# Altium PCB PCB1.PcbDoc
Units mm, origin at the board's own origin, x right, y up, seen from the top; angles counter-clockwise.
Board outline 140.5 x 67.5 mm, 2 copper layers (Top Layer, Bottom Layer); 70 components, 64 nets, 271 pads, 0 vias.
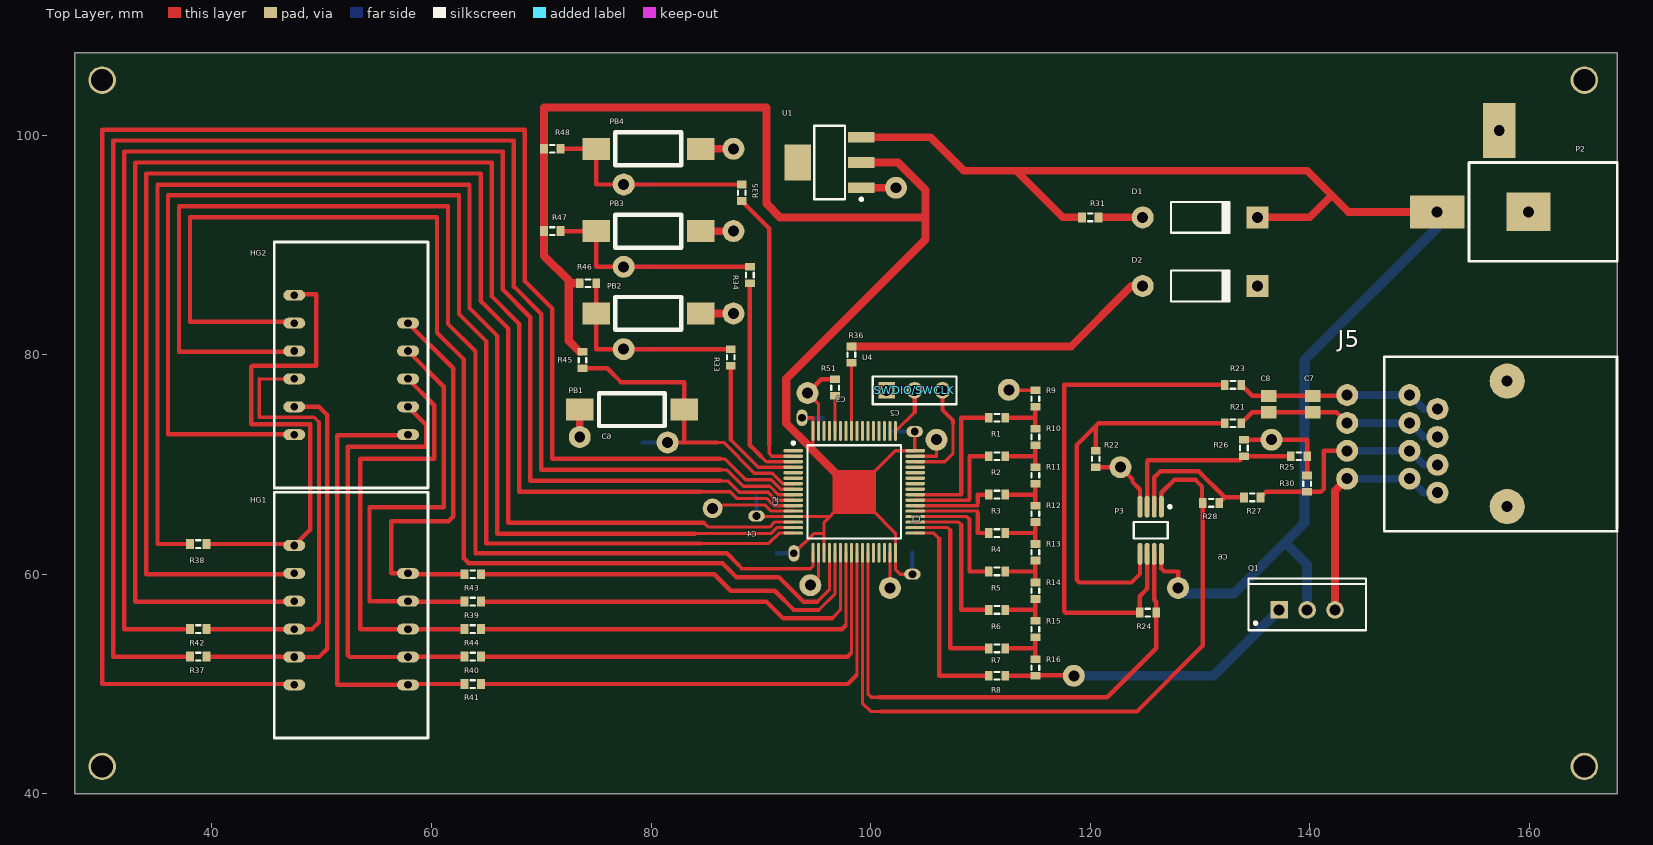
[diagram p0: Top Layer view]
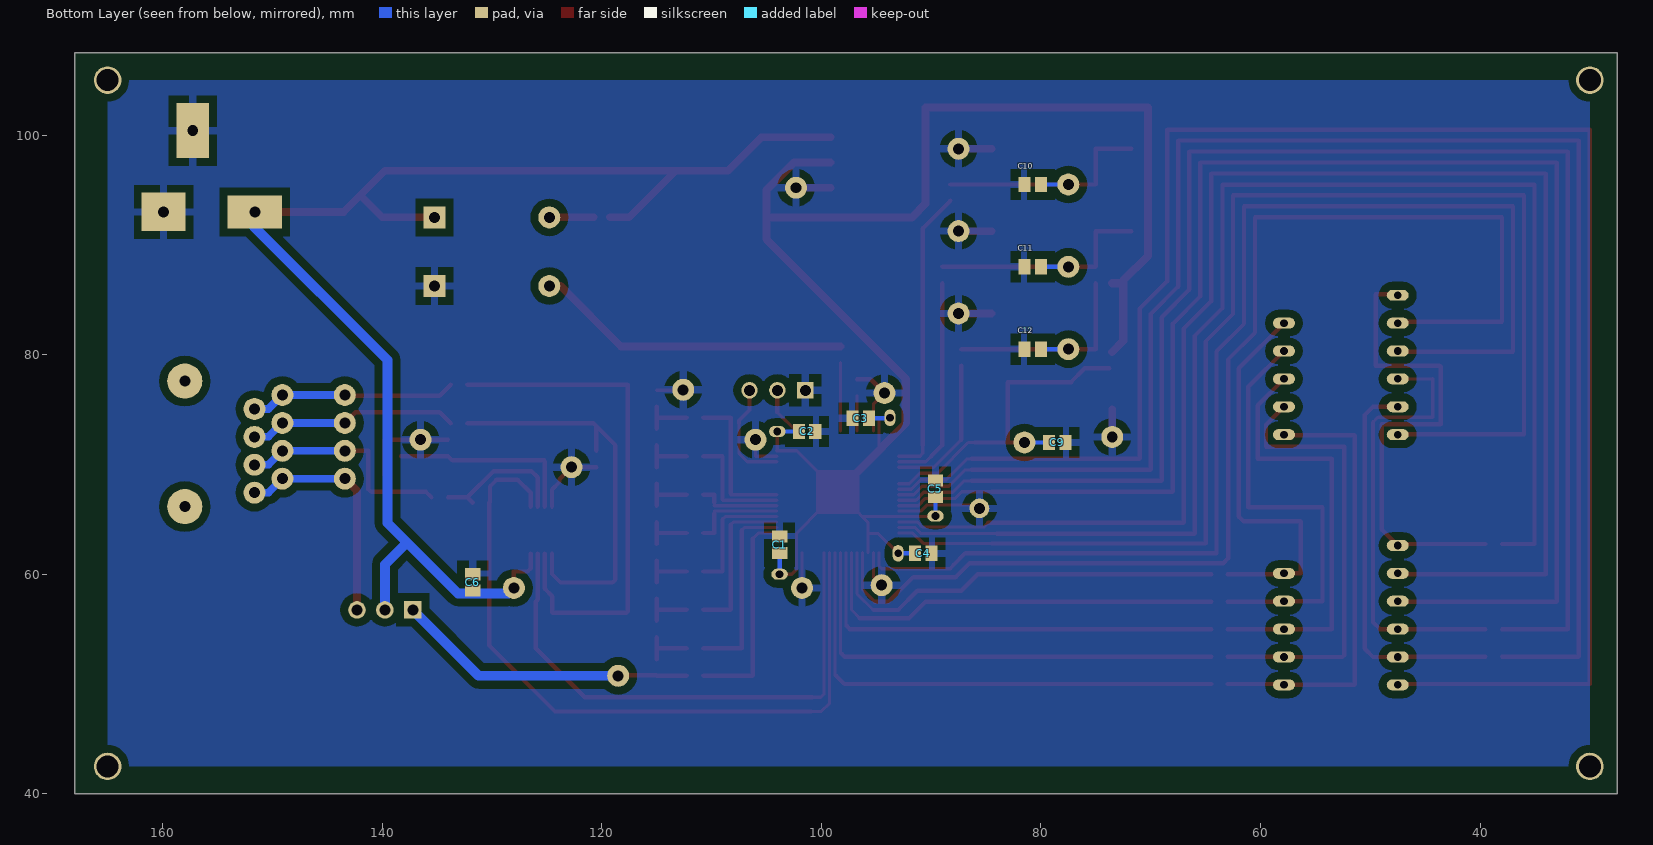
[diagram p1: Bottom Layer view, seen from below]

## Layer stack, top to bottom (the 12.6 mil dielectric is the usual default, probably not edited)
Top Solder: solder mask 0.0102, Solder Resist, Dk 3.5
Top Layer: signal copper 0.0356
Dielectric 1: dielectric 0.32, FR-4, Dk 4.8
Bottom Layer: signal copper 0.0356
Bottom Solder: solder mask 0.0102, Solder Resist, Dk 3.5

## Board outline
168,107.5 167.75,107.5 167.5,107.5 27.5,107.5 27.5,40 168,40

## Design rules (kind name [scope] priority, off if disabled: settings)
Clearance Clearance_Poly [InPolygon] p1: gap=0.7
Clearance [All] p2: gap=0.2
HoleSize [All] p1: absolutevalues=TRUE maxlimit=2.7 minlimit=0.025 maxpercent=80.000 minpercent=20.000
PlaneClearance [All] p1: clearance=0.5
PlaneConnect PlaneConnect_1 [InPolygon] p1: planeconnectstyle=Relief reliefexpansion=0.508 reliefentries=4 reliefconductorwidth=0.5 reliefairgap=0.5
PlaneConnect [All] p2: planeconnectstyle=Relief reliefexpansion=0.508 reliefentries=4 reliefconductorwidth=0.5 reliefairgap=0.5
PolygonConnect [All] p1: connectstyle=Relief reliefconductorwidth=0.7 reliefentries=4 polygonreliefangle="90 Angle" airgapwidth=0.7
RoutingVias [All] p1: holewidth=0.711 width=1.27 viastyle="Through Hole" minholewidth=0.711 minwidth=1.27 maxholewidth=0.711 maxwidth=1.27
SilkToSolderMaskClearance [IsPad] p1: minsilkscreentomaskgap=0 clearancetoexposedcopper=TRUE
SolderMaskExpansion [All] p1: expansion=0.102
Width [All] p1: maxlimit=1 minlimit=0.3 preferedwidth=0.5 minimp=50.000000 maximp=50.000000 favimp=50.000000
26 further rules are at their usual default settings.

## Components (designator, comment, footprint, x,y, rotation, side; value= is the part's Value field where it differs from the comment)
C1 "Cap Pol3" C0805 103.8,62.7 r270 bottom
C2 "Cap Pol3" C0805 101.3,73 r0 bottom
C3 "Cap Pol3" C0805 96.4,74.2 r180 bottom
C4 "Cap Pol3" C0805 90.7,61.9 r0 bottom
C5 "Cap Pol3" C0805 89.6,67.8 r270 bottom
C6 "Cap Pol3" C0805 131.75,59.25 r270 bottom
C7 "Cap Pol3" C0805 140.25,75.5 r90 top
C8 "Cap Pol3" C0805 136.25,75.5 r90 top
C9 "Cap Pol3" C0805 78.5,72 r0 bottom
C10 "Cap Pol3" C0805 80.75,95.5 r0 bottom
C11 "Cap Pol3" C0805 80.75,88 r0 bottom
C12 "Cap Pol3" C0805 80.75,80.5 r0 bottom
D1 "Diode 1N4001" DO-41 130,92.5 r0 top
D2 "Diode 1N4001" DO-41 130,86.25 r0 top
HG1 "rl-t3620" ? 59.68,45.07 r90 top
HG2 "rl-t3620" ? 59.68,67.86 r90 top
J5 "RJ-45" RJ_45 167.975,79.815 r180 top
P2 "Power Jack" PCBCOMPONENT_1 168,97.5 r180 top
P3 "Component_1" MSOP-8 125.5,64 r270 top
PB1 "PB" BUTTON1 81.25,76.5 r180 top
PB2 "PB" BUTTON1 82.75,85.25 r180 top
PB3 "PB" BUTTON1 82.75,92.75 r180 top
PB4 "PB" BUTTON1 82.75,100.25 r180 top
Q1 "IRL3705N" TO-220AB 139.75,56.75 r0 top
R1 "Res3" J1-0603 111.5,74.25 r0 top
R2 "Res3" J1-0603 111.5,70.75 r0 top
R3 "Res3" J1-0603 111.5,67.25 r0 top
R4 "Res3" J1-0603 111.5,63.75 r0 top
R5 "Res3" J1-0603 111.5,60.25 r0 top
R6 "Res3" J1-0603 111.5,56.75 r0 top
R7 "Res3" J1-0603 111.5,53.25 r0 top
R8 "Res3" J1-0603 111.5,50.75 r0 top
R9 "Res3" J1-0603 115,76 r270 top
R10 "Res3" J1-0603 115,72.5 r270 top
R11 "Res3" J1-0603 115,69 r270 top
R12 "Res3" J1-0603 115,65.5 r270 top
R13 "Res3" J1-0603 115,62 r270 top
R14 "Res3" J1-0603 115,58.5 r270 top
R15 "Res3" J1-0603 115,55 r270 top
R16 "Res3" J1-0603 115,51.5 r270 top
R21 "Res3" J1-0603 133,73.75 r0 top
R22 "Res3" J1-0603 120.5,70.5 r90 top
R23 "Res3" J1-0603 133,77.25 r0 top
R24 "Res3" J1-0603 125.25,56.5 r180 top
R25 "Res3" J1-0603 139,70.75 r0 top
R26 "Res3" J1-0603 134,71.5 r270 top
R27 "Res3" J1-0603 134.75,67 r0 top
R28 "Res3" J1-0603 131,66.5 r0 top
R30 "Res3" J1-0603 139.75,68.25 r270 top
R31 "Res3" J1-0603 120,92.5 r180 top
R33 "Res3" J1-0603 87.25,79.75 r90 top
R34 "Res3" J1-0603 89,87.25 r90 top
R35 "Res3" J1-0603 88.25,94.75 r90 top
R36 "Res3" J1-0603 98.25,80 r270 top
R37 "Res3" J1-0603 38.75,52.5 r180 top
R38 "Res3" J1-0603 38.75,62.75 r180 top
R39 "Res3" J1-0603 63.75,57.5 r0 top
R40 "Res3" J1-0603 63.75,52.5 r0 top
R41 "Res3" J1-0603 63.75,50 r0 top
R42 "Res3" J1-0603 38.75,55 r180 top
R43 "Res3" J1-0603 63.75,60 r0 top
R44 "Res3" J1-0603 63.75,55 r0 top
R45 "Res3" J1-0603 73.75,79.5 r270 top
R46 "Res3" J1-0603 74.25,86.5 r180 top
R47 "Res3" J1-0603 71,91.25 r180 top
R48 "Res3" J1-0603 71,98.75 r180 top
R51 "Res3" J1-0603 96.75,77 r90 top
SWDIO/SWCLK "Header 3" HDR1X3 101.46,76.75 r0 top
U1 "1117IS-3.3" SOT223_N 96.25,97.5 r180 top
U4 "STM32F103RBT6" LQFP64_N 98.5,67.5 r0 top

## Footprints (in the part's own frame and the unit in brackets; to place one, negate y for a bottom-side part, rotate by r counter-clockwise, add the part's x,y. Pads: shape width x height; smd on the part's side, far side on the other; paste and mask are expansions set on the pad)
BUTTON1 [mm]
  rect 2.5x2 smd: 0(-1.75,1.5) 1(7.75,1.5)
  silkscreen extent 0,0 6,3
C0805 [mm] "Chip Capacitor, Body 2.0x1.3mm, IPC High Density"
  rect 1.1x1.4 smd: 1(-0.75,0) 2(0.75,0)
  body extent -1.1,-0.72 1.1,0.72, height 1.4
DO-41 [mm] "Diode, Axial; Body 5.2 x 2.7 mm (LxDia. max), Lead Dia. 0.86 mm (max)"
  round 2 hole 1: 1(-5.23,0)
  rect 2x2 hole 1: 2(5.23,0)
  silkscreen extent -2.65,-1.4 2.75,1.4
HDR1X3 [mm] "Connector; Header; 3 Position"
  rect 1.5x1.5 hole 1: 1(0,0)
  round 1.5 hole 1: 2(2.54,0) 3(5.08,0)
  silkscreen extent -1.27,-1.27 6.35,1.27
J1-0603 [mm] "Chip Resistor, Body 1.6x0.8mm, IPC High Density"
  rect 0.7x0.9 smd: 1(-0.75,0) 2(0.75,0)
  silkscreen extent -0.2,-0.35 0.2,0.35, body extent -0.85,-0.48 0.85,0.48, height 0.9
LQFP64_N [mm] "Thin QFP, 64-Leads, Body 10x10mm, Pitch 0.5mm, IPC Medium Density"
  oval 1.8x0.3 smd: 1(-5.55,3.75) 2(-5.55,3.25) 3(-5.55,2.75) 4(-5.55,2.25) 5(-5.55,1.75) 6(-5.55,1.25) 7(-5.55,0.75) 8(-5.55,0.25) 9(-5.55,-0.25) 10(-5.55,-0.75) 11(-5.55,-1.25) 12(-5.55,-1.75) 13(-5.55,-2.25) 14(-5.55,-2.75) 15(-5.55,-3.25) 16(-5.55,-3.75) 33(5.55,-3.75) 34(5.55,-3.25) 35(5.55,-2.75) 36(5.55,-2.25) 37(5.55,-1.75) 38(5.55,-1.25) 39(5.55,-0.75) 40(5.55,-0.25) 41(5.55,0.25) 42(5.55,0.75) 43(5.55,1.25) 44(5.55,1.75) 45(5.55,2.25) 46(5.55,2.75) 47(5.55,3.25) 48(5.55,3.75)
  oval 0.3x1.8 smd: 17(-3.75,-5.55) 18(-3.25,-5.55) 19(-2.75,-5.55) 20(-2.25,-5.55) 21(-1.75,-5.55) 22(-1.25,-5.55) 23(-0.75,-5.55) 24(-0.25,-5.55) 25(0.25,-5.55) 26(0.75,-5.55) 27(1.25,-5.55) 28(1.75,-5.55) 29(2.25,-5.55) 30(2.75,-5.55) 31(3.25,-5.55) 32(3.75,-5.55) 49(3.75,5.55) 50(3.25,5.55) 51(2.75,5.55) 52(2.25,5.55) 53(1.75,5.55) 54(1.25,5.55) 55(0.75,5.55) 56(0.25,5.55) 57(-0.25,5.55) 58(-0.75,5.55) 59(-1.25,5.55) 60(-1.75,5.55) 61(-2.25,5.55) 62(-2.75,5.55) 63(-3.25,5.55) 64(-3.75,5.55)
  silkscreen extent -5.67,-4.25 4.25,4.57, body extent -5,-5 5,5, height 1.6
MSOP-8 [mm] "TSOP, 8-Leads, Body 3x3mm, Pitch 0.65mm, IPC Low Density"
  oval 2x0.45 smd: 1(-2.15,0.975) 2(-2.15,0.325) 3(-2.15,-0.325) 4(-2.15,-0.975) 5(2.15,-0.975) 6(2.15,-0.325) 7(2.15,0.325) 8(2.15,0.975)
  silkscreen extent -2.27,-1.55 0.75,1.88, body extent -1.55,-1.55 1.55,1.55, height 1.1
PCBCOMPONENT_1 [mm]
  rect 5x3 hole 1: 1(16.4,4.5)
  rect 3x5 hole 1: 2(10.75,-2.9)
  rect 4x3.5 hole 1: 3(8.1,4.5)
  silkscreen extent 0,0 13.5,9
RJ_45 [mm]
  round 2 hole 1: 1(16.35,12.385) 1(18.89,11.115) 1(24.575,11.115) 2(16.35,9.845) 2(18.89,8.575) 2(24.575,8.575) 3(16.35,7.305) 3(18.89,6.035) 3(24.575,6.035) 4(16.35,4.765) 4(18.89,3.495) 4(24.575,3.495)
  round 3.2 hole 1: 11(10,2.225) 12(10,13.655)
  Bottom Layer lines w0.7: 24.575,11.115 18.89,11.115 17.62,12.385 16.35,12.385 ; 24.575,8.575 18.89,8.575 17.62,9.845 16.35,9.845 ; 24.575,6.035 18.89,6.035 17.62,7.305 16.35,7.305 ; 24.575,3.495 18.89,3.495 17.62,4.765 16.35,4.765
  silkscreen extent 0,0 21.2,15.9
SOT223_N [mm] "SOT223, 4-Leads, Body 6.5x3.5mm, Pitch 2.3mm, Lead Span 7mm, IPC Medium Density"
  rect 2.4x1 smd: 1(-2.9,2.3) 2(-2.9,0) 3(-2.9,-2.3)
  rect 2.4x3.3 smd: 4(2.9,0)
  silkscreen extent -3.03,-3.35 1.4,3.47, body extent -1.85,-3.35 1.85,3.35, height 1.7
TO-220AB [mm] "TO, Thru-Hole, Vertical, Heatsink Mounted; 3 In-Line Leads; Pitch 2.54 mm"
  rect 1.6x1.6 hole 1: 1(-2.54,0)
  round 1.6 hole 1: 2(0,0) 3(2.54,0)
  silkscreen extent -5.35,-1.85 5.35,2.85, body extent -5.4,-1.9 5.4,2.9, height 19.3
? [mm]
  oval 1x2 hole 0.7: 1(4.85,1.82) 2(7.39,1.82) 3(9.93,1.82) 4(12.47,1.82) 5(15.01,1.82) 7(17.55,12.18) 8(15.01,12.18) 9(12.47,12.18) 10(9.93,12.18) 11(7.39,12.18) 12(4.85,12.18)
  silkscreen extent 0,0 22.4,14

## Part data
C1 C2 C3 C4 C5 C6 C7 C8 C9 C10 C11 C12: "Polarized Capacitor (Surface Mount)"
D1 D2: "1 Amp General Purpose Rectifier"
P2: library part Component_1
PB1 PB2 PB3 PB4: library part button1
Q1: "HEXFET Power MOSFET"
R1 R2 R3 R4 R5 R6 R7 R8 R9 R10 R11 R12 R13 R14 R15 R16 R21 R22 R23 R24 R25 R26 R27 R28 R30 R31 R33 R34 R35 R36 R37 R38 R39 R40 R41 R42 R43 R44 R45 R46 R47 R48 R51: "Resistor"
SWDIO/SWCLK: "Header, 3-Pin"
U4: "STM32 ARM-based 32-bit MCU with 128 Kbytes Flash, 64-pin LQFP, Industrial Temperature"

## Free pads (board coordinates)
  round 2.5 hole 2: 0(30,105) 1(30,42.5) 2(165,42.5) 3(165,105)
  round 2 hole 1: 0(73.5,72.5) 0(77.5,80.5) 0(77.5,88) 0(77.5,95.5) 0(81.5,72) 0(87.5,83.75) 0(87.5,91.25) 0(87.5,98.75) 0(94.25,76.5) 0(94.5,59) 0(101.75,58.75) 0(102.3,95.2) 0(106,72.25) 0(112.575,76.8) 0(118.5,50.75) 0(122.75,69.75) 0(128,58.75) 0(136.5,72.25)
  round 1.8 hole 1: 0(85.6,66)
  oval 1.5x1 hole 0.7: 0(89.6,65.3) 0(103.8,60) 0(104,73)
  oval 1x1.5 hole 0.7: 0(93,61.9) 0(93.75,74.25)

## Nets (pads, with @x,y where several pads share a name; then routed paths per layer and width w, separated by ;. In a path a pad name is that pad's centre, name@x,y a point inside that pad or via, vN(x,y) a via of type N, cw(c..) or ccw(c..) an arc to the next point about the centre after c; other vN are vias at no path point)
GND: C1.1 C2.1 C3.1 C4.1 C5.1 C6.1 C9.1 C10.2 C11.2 C12.2 D2.2 P2.2 P2.3 P3.4 pad.0@73.5,72.5 pad.0@85.6,66 pad.0@87.5,83.75 pad.0@87.5,91.25 pad.0@87.5,98.75 pad.0@94.5,59 pad.0@94.25,76.5 pad.0@101.75,58.75 pad.0@102.3,95.2 pad.0@106,72.25 pad.0@112.575,76.8 pad.0@122.75,69.75 pad.0@136.5,72.25 PB1.1 PB2.0 PB3.0 PB4.0 R9.1 R22.1 R25.2 R26.1 R30.1 R51.2 SWDIO/SWCLK.1 U1.1 U4.12 U4.18 U4.31 U4.47 U4.63 | length 57.1
  Top Layer w0.3: pad.0@85.6,66 86.2,66 86.5,66.3 90.407,66.3 90.957,65.75 U4.12 ; pad.0@94.25,76.5 95.25,75.5 U4.63 ; pad.0@94.5,59 95.25,59.75 U4.18 ; pad.0@101.75,58.75 U4.31 ; U4.47 106,70.75 pad.0@106,72.25 ; pad.0@112.575,76.8 112.625,76.75 R9.1
  Top Layer w0.4: pad.0@94.25,76.5 95.5,77.75 R51.2 ; R22.1 122.75,69.75 123.845,68.655 123.845,68.405 124.5,67.75 ; P3.4 124.525,67.725 ; R26.1 136.5,72.25 139.75,72.25 R25.2 R30.1
  Top Layer w0.7: pad.0@73.5,72.5 PB1.1 ; PB2.0 pad.0@87.5,83.75 ; PB3.0 pad.0@87.5,91.25 ; PB4.0 pad.0@87.5,98.75 ; U1.1 pad.0@102.3,95.2
NetC1_2: C1.2 C2.2 C3.2 C4.2 C5.2 pad.0@89.6,65.3 pad.0@93,61.9 pad.0@93.75,74.25 pad.0@103.8,60 pad.0@104,73 R45.1 R46.2 R47.2 R48.2 U1.2 U4.13 U4.19 U4.32 U4.48 U4.64 | length 150.9
  Top Layer w0.3: pad.0@89.6,65.3 89.65,65.25 U4.13 96.25,65.25 ; pad.0@93,61.9 94.8,63.7 95.75,63.7 ; pad.0@93.75,74.25 94.75,74.25 U4.64 94.75,71.25 ; U4.19 95.75,63.7 ; 96.7,65.7 96.25,65.25 ; 99.7,68.7 102.25,71.25 U4.48 ; 100.1,65.9 102.25,63.75 U4.32 102.25,60.45 102.7,60 pad.0@103.8,60 ; U4.48@104,71.3 pad.0@104,73 ; 95.75,63.7 95.75,64.75 96.25,65.25
  Top Layer w0.4: U1.2@99,97.5 U1.2
  Top Layer w0.75: 72.75,86.5 R46.2 ; R45.1@73.5,80.25 72.5,81.25 72.5,86.75 70.25,89 70.25,102.5 90.5,102.5 90.5,93.75 91.75,92.5 105,92.5 ; 96.75,69.25 94.75,71.25 94.479,71.521 94.479,71.573 92.302,73.75 92.302,77.802 105,90.5 105,92.5 ; U1.2 102.5,97.5 105,95 105,92.5
  Bottom Layer w0.4: pad.0@89.6,65.3 C5.2 ; C4.2 pad.0@93,61.9 ; pad.0@93.75,74.25 93.8,74.2 C3.2 ; C2.2 pad.0@104,73 ; pad.0@103.8,60 C1.2
NetC6_2: C6.2 D1.2 P2.1 P3.8 pad.0@128,58.75 Q1.2 R31.2 U1.3 | length 129.9
  Top Layer w0.4: P3.8 126.475,60.525 126.75,60.25 128,60.25 pad.0@128,58.75
  Top Layer w0.7: U1.3 105.45,99.8 108.5,96.75 113.25,96.75 ; R31.2 117.5,92.5 113.25,96.75 ; D1.2 140,92.5 142,94.5 ; P2.1@151.7,93 143.5,93 142,94.5 ; 113.25,96.75 139.75,96.75 142,94.5
  Bottom Layer w0.9: pad.0@128,58.75 128.5,58.25 133.099,58.25 137.75,62.901 ; Q1.2 139.75,60.901 137.75,62.901 ; P2.1@151.7,93 151.7,91.7 139.5,79.5 139.5,64.651 137.75,62.901
NetC7_1: C7.1 C8.1 J5.3 R21.2 | length 10.5
  Top Layer w0.4: R21.2 134.75,74.75 C8.1 139.75,74.75 C7.1 142.43,74.75 J5.3@143.4,73.78
NetC7_2: C7.2 C8.2 J5.4 R23.2 | length 10
  Top Layer w0.4: R23.2 134.75,76.25 C8.2 C7.2 J5.4@143.33,76.25
NetC9_2: C9.2 pad.0@81.5,72 PB1.0 R45.2 U4.7 | length 30.5
  Top Layer w0.3: 86,72 86.6,72 89.4,69.2 91.043,69.2 91.993,68.25 U4.7
  Top Layer w0.4: R45.2 76,78.75 77.25,77.5 83,77.5 PB1.0 83,72 ; pad.0@81.5,72 83,72 ; 86,72 83,72
  Bottom Layer w0.4: C9.2 pad.0@81.5,72
NetC10_1: C10.1 pad.0@77.5,95.5 PB4.1 R35.2 R48.1 | length 22.2
  Top Layer w0.4: R48.1 PB4.1 75,95.5 77.5,95.5 R35.2
  Bottom Layer w0.4: pad.0@77.5,95.5 C10.1
NetC11_1: C11.1 pad.0@77.5,88 PB3.1 R34.2 R47.1 | length 23
  Top Layer w0.4: R47.1 PB3.1 75,88 77.5,88 R34.2
  Bottom Layer w0.4: pad.0@77.5,88 C11.1
NetC12_1: C12.1 pad.0@77.5,80.5 PB2.1 R33.2 R46.1 | length 20.7
  Top Layer w0.4: R46.1 PB2.1 75,80.5 77.5,80.5 R33.2
  Bottom Layer w0.4: pad.0@77.5,80.5 C12.1
NetD1_1: D1.1 R31.1 | length 4
  Top Layer w0.7: R31.1 D1.1
NetD2_1: D2.1 R36.1 | length 27.8
  Top Layer w0.7: R36.1 118.25,80.75 123.75,86.25
NetHG1_1: HG1.1 HG2.1 R41.1 | length 40.9
  Top Layer w0.4: HG2.1 57.82,72.67 51.4,72.67 51.4,49.92 HG1.1 57.94,50 R41.1
NetHG1_2: HG1.2 HG2.2 R40.1 | length 41.1
  Top Layer w0.4: HG1.2 52.54,52.46 52.382,52.618 52.382,71.628 59.5,71.628 59.5,73.61 HG2.2 ; HG1.2@57.9,52.5 R40.1
NetHG1_3: HG1.3 HG2.3 R44.1 | length 40
  Top Layer w0.4: HG2.3 60.25,75.4 60.25,70.5 53.5,70.5 53.5,55 HG1.3 R44.1
NetHG1_4: HG1.4 HG2.4 R39.1 | length 39.5
  Top Layer w0.4: HG1.4 54.354,57.54 54.354,66.104 61.104,66.104 61.104,77.086 HG2.4 ; HG1.4@57.9,57.5 R39.1
NetHG1_5: HG1.5 HG2.5 R43.1 | length 36.5
  Top Layer w0.4: HG1.5 56.33,60.08 56.33,64.83 61.548,64.83 61.968,65.25 61.968,78.762 HG2.5 ; HG1.5@57.94,60 R43.1
NetHG1_7: HG1.7 HG2.7 R38.1 | length 44.3
  Top Layer w0.4: R38.1 HG1.7@47.37,62.75 ; 43.586,78.914 43.586,73.664 48.936,73.664 48.936,64.056 HG1.7 ; 43.672,79 49.5,79 49.5,85.5 HG2.7@47.59,85.5
NetHG1_8: HG1.8 U4.14 | length 139.6
  Top Layer w0.3: 84.8,64.7 85.2,64.3 90.786,64.3 91.236,64.75 U4.14
  Top Layer w0.4: HG1.8@47.42,60 38,60 34,60 34,96.5 64.5,96.5 64.5,84.866 67,82.366 67,64.7 84.8,64.7
NetHG1_9: HG1.9 U4.11 | length 143.5
  Top Layer w0.3: 84.5,67.5 87.2,67.5 87.8,66.9 90.514,66.9 91.164,66.25 U4.11
  Top Layer w0.4: HG1.9@47.46,57.5 33,57.5 33,97.5 65.5,97.5 65.5,85.3 68,82.8 68,67.5 84.5,67.5
NetHG1_10: HG1.10 HG2.10 R42.1 | length 41.1
  Top Layer w0.3: HG2.10 44.31,77.79 44.3,77.8 44.3,74.3 49.3,74.3 49.75,73.85
  Top Layer w0.4: R42.1 HG1.10 49.119,55 49.75,55.631 49.75,73.85
NetHG1_11: HG1.11 HG2.11 R37.1 | length 35.9
  Top Layer w0.4: R37.1 HG1.11@47.46,52.5 ; HG1.11 49.75,52.46 50.5,53.21 50.5,74.5 49.75,75.25 HG2.11
NetHG1_12: HG1.12 U4.8 | length 160.5
  Top Layer w0.3: 86.3,70.5 86.7,70.5 88.6,68.6 90.936,68.6 91.786,67.75 U4.8
  Top Layer w0.4: HG1.12@47.42,50 30,50 30,100.5 68.5,100.5 68.5,86.7 71,84.2 71,70.5 86.3,70.5
NetHG2_8: HG2.8 U4.20 | length 112.4
  Top Layer w0.3: 95.123,57.496 96.25,58.623 U4.20
  Top Layer w0.4: HG2.8 47.37,83 38,83 38,92.5 60.5,92.5 60.5,82 62.946,79.554 62.946,61.454 63.4,61 86.5,61 87.758,59.742 91.631,59.742 93.877,57.496 95.123,57.496
NetHG2_9: HG2.9 U4.17 | length 113.5
  Top Layer w0.3: 88,60.8 88.2,60.6 88.2,60.5 94.5,60.5 94.75,60.75 U4.17
  Top Layer w0.4: HG2.9@47.42,80.25 39.5,80.25 37,80.25 37,93.5 61.5,93.5 61.5,82.8 64,80.3 64,61.9 86.9,61.9 88,60.8
NetHG2_12: HG2.12 U4.16 | length 120.8
  Top Layer w0.3: 84.5,62.8 90.7,62.8 91.65,63.75 U4.16
  Top Layer w0.4: HG2.12@47.46,72.75 36,72.75 36,94.5 62.5,94.5 62.5,83.7 65,81.2 65,62.8 84.5,62.8
NetJ5_1: J5.1 Q1.3 | length 12.4
  Top Layer w0.7: Q1.3 142.29,67.59 J5.1@143.4,68.7
NetJ5_2: J5.2 R27.2 R30.2 | length 11.7
  Top Layer w0.4: R27.2 136,67.5 R30.2 141,67.5 141.25,67.75 141.25,70.75 141.25,71.25 143.39,71.25 J5.2@143.4,71.24
NetP3_1: P3.1 R28.1 U4.26 | length 67.6
  Top Layer w0.3: U4.26 99.25,48.25 100,47.5 100.9,47.5
  Top Layer w0.4: 100.9,47.5 124.25,47.5 130.25,53.5 R28.1 ; P3.1 126.475,67.41 127.655,68.59 129.59,68.59 130.18,68 R28.1@130.18,66.57
NetP3_2: P3.2 R27.1 R28.2 | length 12.8
  Top Layer w0.4: P3.2 125.825,68.825 126.385,69.385 129.865,69.385 132.25,67 ; R28.2 132.25,67 ; R27.1 132.25,67
NetP3_3: P3.3 R25.1 R26.2 | length 17.3
  Top Layer w0.4: P3.3 125.175,70.29 ; 125.25,70.365 133.615,70.365 R26.2 R25.1
NetP3_5: P3.5 R21.1 R22.2 | length 36.9
  Top Layer w0.4: R22.2 120.5,73.5 ; P3.5 124.525,60.025 123.75,59.25 119,59.25 118.75,59.5 118.75,71.75 120.5,73.5 ; R21.1 120.75,73.75 120.5,73.5
NetP3_6: P3.6 R23.1 R24.2 | length 47.8
  Top Layer w0.4: P3.6 125.175,58.675 125.115,58.615 124.5,58 R24.2 117.75,56.5 117.635,56.615 117.635,77.25 R23.1
NetP3_7: P3.7 R24.1 U4.27 | length 49.7
  Top Layer w0.3: U4.27 99.75,49.1 100.05,48.8 100.796,48.8
  Top Layer w0.4: 100.8,48.804 121.554,48.804 126,53.25 R24.1 126,57.5 125.825,57.675 P3.7
NetQ1_1: pad.0@118.5,50.75 Q1.1 R8.2 R16.2 | length 27.3
  Top Layer w0.4: R8.2 R16.2 ; R16.2@115.05,50.8 pad.0@118.45,50.8
  Bottom Layer w0.9: pad.0@118.5,50.75 131.21,50.75 Q1.1
NetR1_1: R1.1 U4.40 | length 13.6
  Top Layer w0.3: U4.40 108.25,67.25
  Top Layer w0.4: 108.25,67.35 108.25,74.25 R1.1
NetR1_2: R1.2 R9.2 R10.1 | length 4.8
  Top Layer w0.4: R1.2 115,74.25 ; R10.1 R9.2
NetR2_1: R2.1 U4.39 | length 10.6
  Top Layer w0.3: U4.39 109,66.75
  Top Layer w0.4: 109,66.85 109,70.75 R2.1
NetR2_2: R2.2 R10.2 R11.1 | length 4.7
  Top Layer w0.4: R2.2 115,70.75 ; R11.1 R10.2
NetR3_1: R3.1 U4.38 | length 7.5
  Top Layer w0.3: U4.38 109.75,66.25
  Top Layer w0.4: 109.75,66.5 109.75,67.25 R3.1
NetR3_2: R3.2 R11.2 R12.1 | length 4.7
  Top Layer w0.4: R3.2 115,67.25 ; R12.1 R11.2
NetR4_1: R4.1 U4.37 | length 8.4
  Top Layer w0.3: U4.37 109.75,65.75
  Top Layer w0.4: 109.75,65.5 109.75,63.75 R4.1
NetR4_2: R4.2 R12.2 R13.1 | length 4.8
  Top Layer w0.4: R4.2 115,63.75 ; R13.1 R12.2
NetR5_1: R5.1 U4.36 | length 11.6
  Top Layer w0.3: U4.36 108.75,65.25 109,65
  Top Layer w0.4: 109,65 109,60.5 109,60.25 R5.1
NetR5_2: R5.2 R13.2 R14.1 | length 4.8
  Top Layer w0.4: R5.2 115,60.25 ; R14.1 R13.2
NetR6_1: R6.1 U4.35 | length 14.6
  Top Layer w0.3: U4.35 108,64.75 108.25,64.5
  Top Layer w0.4: 108.25,64.5 108.25,57 108.25,56.75 R6.1
NetR6_2: R6.2 R14.2 R15.1 | length 4.8
  Top Layer w0.4: R6.2 115,56.75 ; R15.1 R14.2
NetR7_1: R7.1 U4.34 | length 17.6
  Top Layer w0.3: U4.34 107,64.25 107.25,64
  Top Layer w0.4: 107.25,64 107.25,53.25 R7.1
NetR7_2: R7.2 R15.2 R16.1 | length 4.8
  Top Layer w0.4: R7.2 115,53.25 ; R16.1 115,53.25 ; R15.2 115,53.25
NetR8_1: R8.1 U4.33 | length 19.4
  Top Layer w0.3: U4.33 105.75,63.75 106.25,63.25
  Top Layer w0.4: 106.25,63.25 106.25,50.75 R8.1
NetR33_1: R33.1 U4.4 | length 13.5
  Top Layer w0.3: 87.25,72.25 89.75,69.75 U4.4
  Top Layer w0.4: 87.25,72.25 R33.1
NetR34_1: R34.1 U4.3 | length 19.3
  Top Layer w0.3: 90,70.75 90.5,70.25 U4.3
  Top Layer w0.4: R34.1 89,71.75 90,70.75
NetR35_1: R35.1 U4.2 | length 26.3
  Top Layer w0.3: 90.75,71.75 90.75,71 91,70.75 U4.2
  Top Layer w0.4: R35.1 90.75,91.5 90.75,71.75
NetR36_2: R36.2 U4.57 | length 6.2
  Top Layer w0.3: U4.57 R36.2
NetR37_2: R37.2 U4.9 | length 145.4
  Top Layer w0.3: 86.3,69.5 86.9,69.5 88.4,68 90.829,68 91.579,67.25 U4.9
  Top Layer w0.4: R37.2 33.726,52.5 31,52.5 31,99.5 67.5,99.5 67.5,86.2 70,83.7 70,69.5 86.3,69.5
NetR38_2: R38.2 U4.15 | length 124.1
  Top Layer w0.3: 84,63.7 90.893,63.7 91.443,64.25 U4.15
  Top Layer w0.4: R38.2 35.04,62.75 35.04,95.46 63.46,95.46 63.46,84.24 66,81.7 66,63.7 84,63.7
NetR39_2: R39.2 U4.22 | length 38.9
  Top Layer w0.3: 96.488,55.988 97.25,56.75 U4.22
  Top Layer w0.4: R39.2 90.5,57.5 92.012,55.988 96.488,55.988
NetR40_2: R40.2 U4.24 | length 43
  Top Layer w0.3: 98.25,52.75 98.25,54.901 98.25,55.599 U4.24
  Top Layer w0.4: R40.2 97.9,52.5 98.15,52.75
NetR41_2: R41.2 U4.25 | length 45.7
  Top Layer w0.3: 98.75,50.75 U4.25
  Top Layer w0.4: R41.2 97.9,50 98.65,50.75
NetR42_2: R42.2 U4.10 | length 139.7
  Top Layer w0.3: 86.3,68.5 87,68.5 88.039,67.461 90.661,67.461 91.372,66.75 U4.10
  Top Layer w0.4: R42.2 32,55 32,98.5 66.5,98.5 66.5,85.9 69,83.4 69,68.5 86.3,68.5
NetR43_2: R43.2 U4.21 | length 37.9
  Top Layer w0.3: 95.25,56.742 96.75,58.242 U4.21
  Top Layer w0.4: R43.2 85.75,60 87.25,58.5 91.25,58.5 93.008,56.742 95.25,56.742
NetR44_2: R44.2 U4.23 | length 40
  Top Layer w0.3: 97.75,55.25 U4.23
  Top Layer w0.4: R44.2 97.4,55 97.65,55.25
NetR51_1: R51.1 U4.60 | length 3.2
  Top Layer w0.3: U4.60 R51.1
NetSWDIO/SWCLK_2: SWDIO/SWCLK.2 U4.49 | length 4.5
  Top Layer w0.3: U4.49 102.304,73.05 104,74.746
  Top Layer w0.4: 104,74.746 SWDIO/SWCLK.2
NetSWDIO/SWCLK_3: SWDIO/SWCLK.3 U4.46 | length 9.9
  Top Layer w0.3: U4.46 106.75,70.25 107.5,71 107.5,73.75
  Top Layer w0.4: SWDIO/SWCLK.3 106.54,74.96 107.496,74.004 107.496,73.75
pads on no net: J5.11 J5.12 U1.4 U4.1 U4.5 U4.6 U4.28 U4.29 U4.30 U4.41 U4.42 U4.43 U4.44 U4.45 U4.50 U4.51 U4.52 U4.53 U4.54 U4.55 U4.56 U4.58 U4.59 U4.61 U4.62

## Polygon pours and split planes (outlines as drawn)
GND on Bottom Layer "GND" (solid, remove dead copper, pour order 4): 30,105 165,105 165,42.5 30,42.5

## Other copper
Top Layer:
  rectangle net NetC1_2: 96.5,65.5 100.5,69.5

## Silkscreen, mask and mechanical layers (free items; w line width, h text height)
Mechanical 1:
  lines w1.5: 27.5,40 165,40 168,40 168,107.5 27.5,107.5 27.5,40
